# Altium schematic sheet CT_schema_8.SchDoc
size 296 x 258 mm
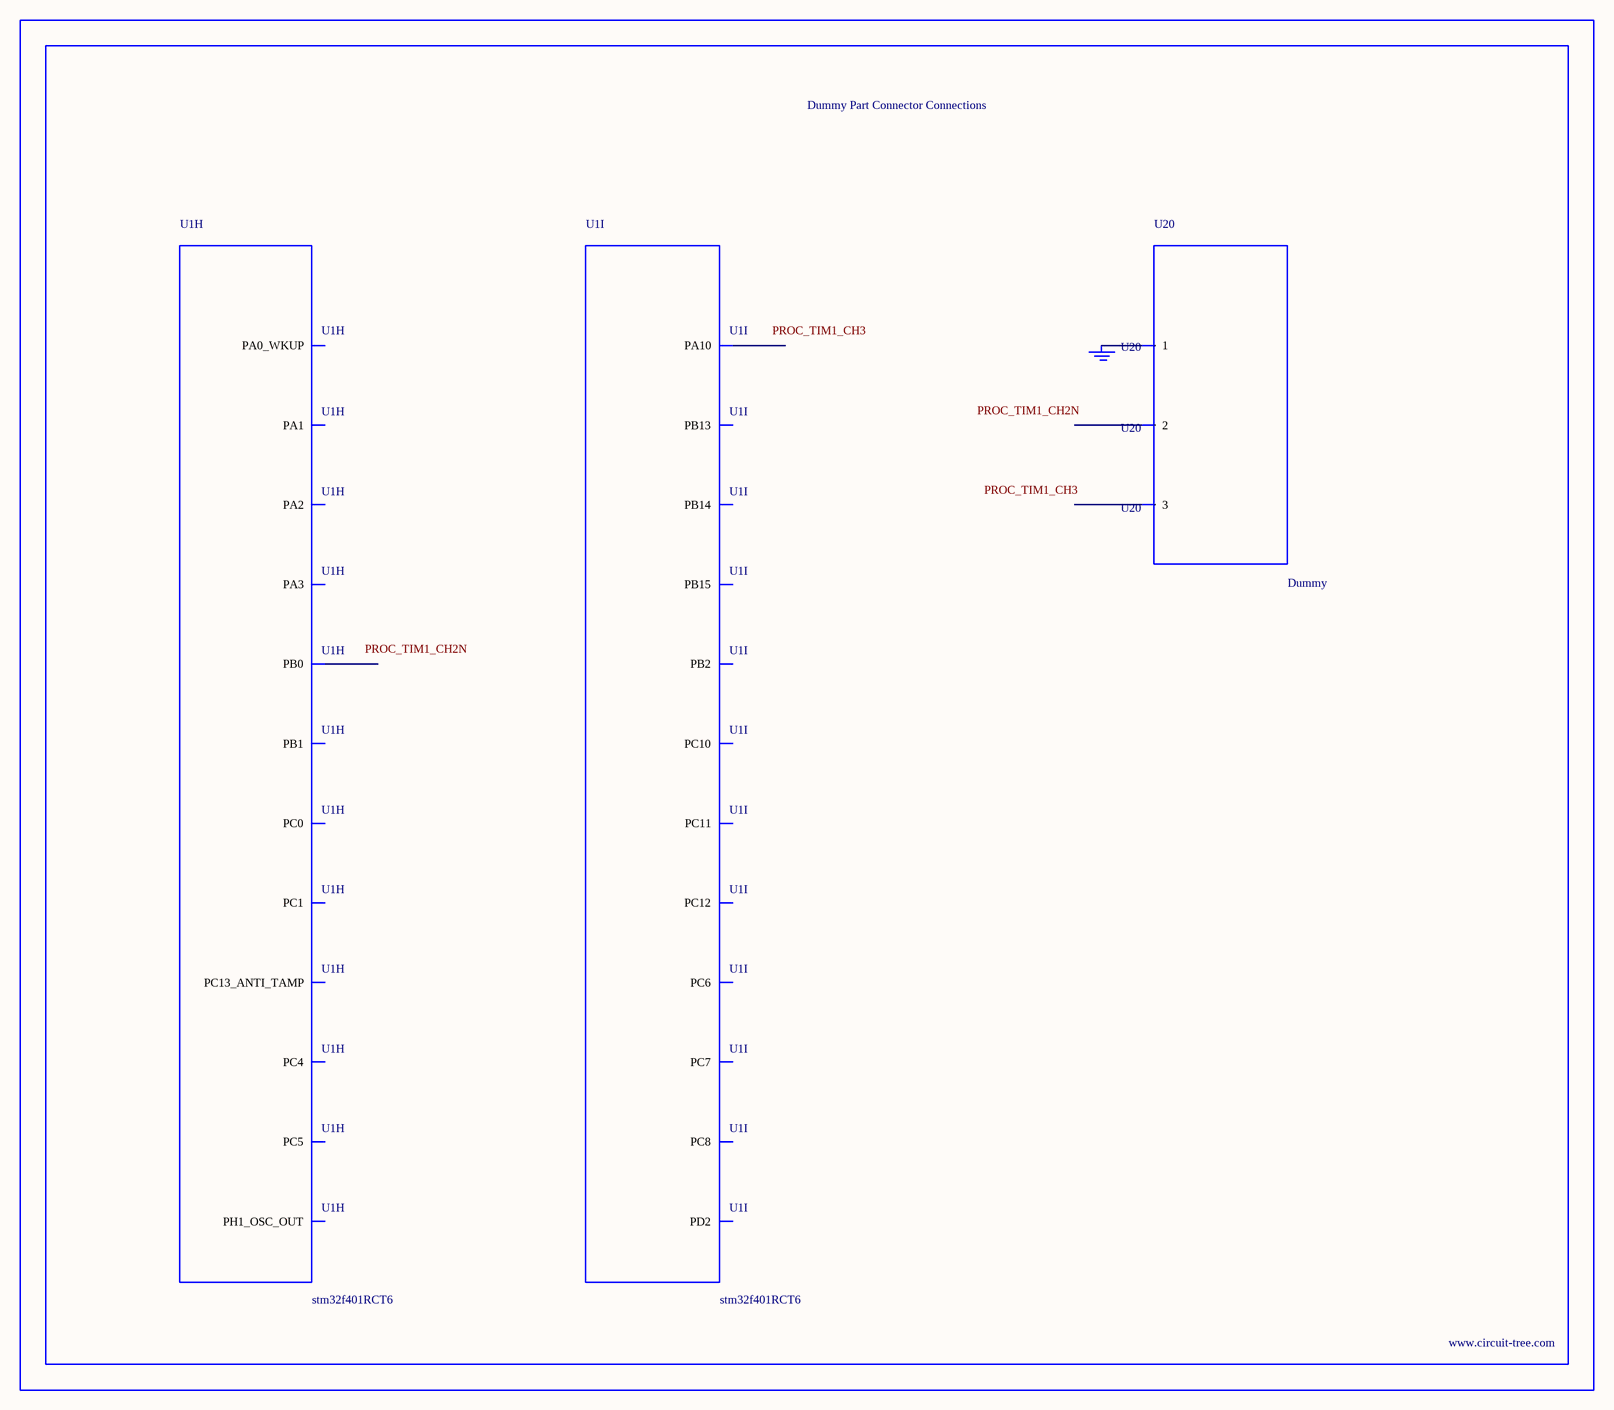
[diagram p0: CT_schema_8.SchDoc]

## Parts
BORDER7  (no value)
GND_INSTANCE_7_0  (no value)
U1  stm32f401RCT6  [LQFP64]  (parts H,I of 9)
U20  Dummy  [DUMMY_PACKAGE_176]

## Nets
NetGND_INSTANCE_7_0_0: GND_INSTANCE_7_0.0(GND) U20.1

Not connected (* = marked no-connect by the designer): U1 2(PC13_ANTI_TAMP) 6(PH1_OSC_OUT) 8(PC0) 9(PC1) 14(PA0_WKUP) 15(PA1) 16(PA2) 17(PA3) 24(PC4) 25(PC5) 26(PB0) 27(PB1) 28(PB2) 34(PB13) 35(PB14) 36(PB15) 37(PC6) 38(PC7) 39(PC8) 43(PA10) 51(PC10) 52(PC11) 53(PC12) 54(PD2); U20 2 3

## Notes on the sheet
- Labels drawn without touching a wire or pin: PROC_TIM1_CH2N, PROC_TIM1_CH3

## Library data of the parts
BORDER7 = BORDER_PAGE7
GND_INSTANCE_7_0 = GND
